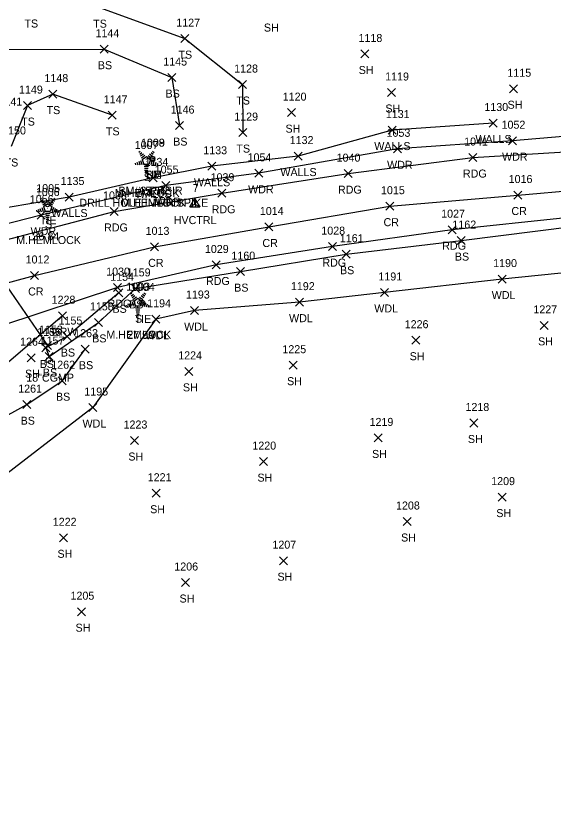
# Model space of a CAD drawing. Extents: x 1621633 to 1624015, y 417863 to 420979.
# Drawn here: x 1622056.7 to 1622191.2, y 417982.6 to 418184 of the extents above; entities that cross this region are included whole.
import ezdxf

# ---------------------------------------------------------------- set-up
doc = ezdxf.new("R2010")
doc.units = 0
for name, color, linetype in [('C_A', 7, 'Continuous'), ('C_C', 7, 'Continuous'), ('C_I', 7, 'Continuous'), ('CBP', 7, 'Continuous'), ('CPBM', 7, 'Continuous'), ('CPSM', 7, 'Continuous'), ('D_A', 7, 'Continuous'), ('D_C', 7, 'Continuous'), ('D_I', 7, 'Continuous'), ('D_TIC', 7, 'Continuous'), ('DCP', 7, 'Continuous'), ('L_A', 7, 'Continuous'), ('L_C', 7, 'Continuous'), ('L_I', 7, 'Continuous'), ('L_TIC', 7, 'Continuous'), ('LAWA', 7, 'Continuous'), ('LELB', 7, 'Continuous'), ('LTC', 7, 'Continuous'), ('LWS', 7, 'Continuous'), ('P_A', 7, 'Continuous'), ('P_I', 7, 'Continuous'), ('P_TIC', 7, 'Continuous'), ('PEU', 7, 'Continuous'), ('PRC', 7, 'Continuous'), ('R_A', 7, 'Continuous'), ('R_I', 7, 'Continuous'), ('R_TIC', 7, 'Continuous'), ('RDW', 7, 'Continuous')]:
    doc.layers.add(name, color=color, linetype=linetype)

msp = doc.modelspace()

# ---------------------------------------------------------------- linework, layer by layer
at = {"layer": 'CBP'}
for centre, radius in [((1622090.77, 418148.39), 0.625), ((1622090.77, 418148.39), 0.0833), ((1622064.59, 418137.03), 0.625), ((1622064.59, 418137.03), 0.0833), ((1622088.28, 418112.35), 0.625), ((1622088.28, 418112.35), 0.0833)]:
    msp.add_circle(centre, radius, dxfattribs=at)
at = {"layer": 'CPBM'}
for p, q in [((1622090.3, 418147.9), (1622090.3, 418148.9)), ((1622090.3, 418148.9), (1622091.3, 418148.9)), ((1622091.3, 418147.9), (1622090.3, 418147.9)), ((1622090.81, 418148.4), (1622090.81, 418148.4)), ((1622090.81, 418148.4), (1622090.81, 418148.4)), ((1622091.3, 418148.9), (1622091.3, 418147.9))]:
    msp.add_line(p, q, dxfattribs=at)
at = {"layer": 'CPSM'}
for p, q in [((1622100.18, 418136.33), (1622101.43, 418138.49)), ((1622102.68, 418136.33), (1622101.43, 418138.49)), ((1622101.43, 418137.05), (1622101.43, 418138.49)), ((1622100.18, 418136.33), (1622101.43, 418137.05)), ((1622100.18, 418136.33), (1622102.68, 418136.33)), ((1622101.43, 418137.05), (1622101.43, 418137.05)), ((1622101.43, 418137.05), (1622102.68, 418136.33))]:
    msp.add_line(p, q, dxfattribs=at)
at = {"layer": 'D_TIC'}
for points in [[(1622063.54, 418100.68), (1622065.54, 418102.68)], [(1622065.54, 418100.68), (1622063.54, 418102.68)]]:
    msp.add_lwpolyline(points, dxfattribs=at)
at = {"layer": 'DCP'}
msp.add_lwpolyline([(1622041.57, 418135.01), (1622064.54, 418101.68)], dxfattribs=at)
at = {"layer": 'L_TIC'}
for points in [[(1622097.9, 418177.4), (1622099.9, 418179.4)], [(1622099.9, 418177.4), (1622097.9, 418179.4)], [(1622077.7, 418174.76), (1622079.7, 418176.76)], [(1622079.7, 418174.76), (1622077.7, 418176.76)], [(1622142.9, 418173.57), (1622144.9, 418175.57)], [(1622144.9, 418173.57), (1622142.9, 418175.57)], [(1622094.64, 418167.67), (1622096.64, 418169.67)], [(1622096.64, 418167.67), (1622094.64, 418169.67)], [(1622112.36, 418165.93), (1622114.36, 418167.93)], [(1622114.36, 418165.93), (1622112.36, 418167.93)], [(1622180.13, 418164.88), (1622182.13, 418166.88)], [(1622182.13, 418164.88), (1622180.13, 418166.88)], [(1622064.92, 418163.54), (1622066.92, 418165.54)], [(1622066.92, 418163.54), (1622064.92, 418165.54)], [(1622149.57, 418163.94), (1622151.57, 418165.94)], [(1622151.57, 418163.94), (1622149.57, 418165.94)], [(1622058.56, 418160.67), (1622060.56, 418162.67)], [(1622060.56, 418160.67), (1622058.56, 418162.67)], [(1622079.75, 418158.24), (1622081.75, 418160.24)], [(1622081.75, 418158.24), (1622079.75, 418160.24)], [(1622124.59, 418158.91), (1622126.59, 418160.91)], [(1622126.59, 418158.91), (1622124.59, 418160.91)], [(1622175.03, 418156.31), (1622177.03, 418158.31)], [(1622177.03, 418156.31), (1622175.03, 418158.31)], [(1622096.55, 418155.67), (1622098.55, 418157.67)], [(1622098.55, 418155.67), (1622096.55, 418157.67)], [(1622112.39, 418153.92), (1622114.39, 418155.92)], [(1622114.39, 418153.92), (1622112.39, 418155.92)], [(1622149.73, 418154.55), (1622151.73, 418156.55)], [(1622151.73, 418154.55), (1622149.73, 418156.55)], [(1622179.88, 418151.89), (1622181.88, 418153.89)], [(1622181.88, 418151.89), (1622179.88, 418153.89)], [(1622126.26, 418148.05), (1622128.26, 418150.05)], [(1622128.26, 418148.05), (1622126.26, 418150.05)], [(1622151.12, 418149.87), (1622153.12, 418151.87)], [(1622153.12, 418149.87), (1622151.12, 418151.87)], [(1622104.64, 418145.5), (1622106.64, 418147.5)], [(1622106.64, 418145.5), (1622104.64, 418147.5)], [(1622089.95, 418142.6), (1622091.95, 418144.6)], [(1622091.95, 418142.6), (1622089.95, 418144.6)], [(1622116.37, 418143.74), (1622118.37, 418145.74)], [(1622118.37, 418143.74), (1622116.37, 418145.74)], [(1622093.14, 418140.69), (1622095.14, 418142.69)], [(1622095.14, 418140.69), (1622093.14, 418142.69)], [(1622068.97, 418137.82), (1622070.97, 418139.82)], [(1622070.97, 418137.82), (1622068.97, 418139.82)], [(1622061.96, 418133.28), (1622063.96, 418135.28)], [(1622063.96, 418133.28), (1622061.96, 418135.28)], [(1622167, 418126.93), (1622169, 418128.93)], [(1622169, 418126.93), (1622167, 418128.93)], [(1622138.27, 418123.52), (1622140.27, 418125.52)], [(1622140.27, 418123.52), (1622138.27, 418125.52)], [(1622111.81, 418119.17), (1622113.81, 418121.17)], [(1622113.81, 418119.17), (1622111.81, 418121.17)], [(1622177.23, 418117.31), (1622179.23, 418119.31)], [(1622179.23, 418117.31), (1622177.23, 418119.31)], [(1622081.36, 418113.88), (1622083.36, 418115.88)], [(1622083.36, 418113.88), (1622081.36, 418115.88)], [(1622085.53, 418114.98), (1622087.53, 418116.98)], [(1622087.53, 418114.98), (1622085.53, 418116.98)], [(1622147.87, 418113.96), (1622149.87, 418115.96)], [(1622149.87, 418113.96), (1622147.87, 418115.96)], [(1622126.56, 418111.54), (1622128.56, 418113.54)], [(1622128.56, 418111.54), (1622126.56, 418113.54)], [(1622100.31, 418109.45), (1622102.31, 418111.45)], [(1622102.31, 418109.45), (1622100.31, 418111.45)], [(1622076.28, 418106.48), (1622078.28, 418108.48)], [(1622078.28, 418106.48), (1622076.28, 418108.48)], [(1622090.62, 418107.26), (1622092.62, 418109.26)], [(1622092.62, 418107.26), (1622090.62, 418109.26)], [(1622187.76, 418105.74), (1622189.76, 418107.74)], [(1622189.76, 418105.74), (1622187.76, 418107.74)], [(1622068.44, 418102.95), (1622070.44, 418104.95)], [(1622070.44, 418102.95), (1622068.44, 418104.95)], [(1622155.64, 418102.03), (1622157.64, 418104.03)], [(1622157.64, 418102.03), (1622155.64, 418104.03)], [(1622063.16, 418100.09), (1622065.16, 418102.09)], [(1622065.16, 418100.09), (1622063.16, 418102.09)], [(1622072.97, 418099.79), (1622074.97, 418101.79)], [(1622074.97, 418099.79), (1622072.97, 418101.79)], [(1622059.44, 418097.66), (1622061.44, 418099.66)], [(1622061.44, 418097.66), (1622059.44, 418099.66)], [(1622063.96, 418097.95), (1622065.96, 418099.95)], [(1622065.96, 418097.95), (1622063.96, 418099.95)], [(1622124.99, 418095.79), (1622126.99, 418097.79)], [(1622126.99, 418095.79), (1622124.99, 418097.79)], [(1622098.94, 418094.24), (1622100.94, 418096.24)], [(1622100.94, 418094.24), (1622098.94, 418096.24)], [(1622067.24, 418091.91), (1622069.24, 418093.91)], [(1622069.24, 418091.91), (1622067.24, 418093.91)], [(1622058.4, 418085.93), (1622060.4, 418087.93)], [(1622060.4, 418085.93), (1622058.4, 418087.93)], [(1622074.89, 418085.21), (1622076.89, 418087.21)], [(1622076.89, 418085.21), (1622074.89, 418087.21)], [(1622170.22, 418081.34), (1622172.22, 418083.34)], [(1622172.22, 418081.34), (1622170.22, 418083.34)], [(1622146.24, 418077.61), (1622148.24, 418079.61)], [(1622148.24, 418077.61), (1622146.24, 418079.61)], [(1622085.28, 418076.96), (1622087.28, 418078.96)], [(1622087.28, 418076.96), (1622085.28, 418078.96)], [(1622117.57, 418071.69), (1622119.57, 418073.69)], [(1622119.57, 418071.69), (1622117.57, 418073.69)], [(1622090.74, 418063.79), (1622092.74, 418065.79)], [(1622092.74, 418063.79), (1622090.74, 418065.79)], [(1622177.3, 418062.82), (1622179.3, 418064.82)], [(1622179.3, 418062.82), (1622177.3, 418064.82)], [(1622153.49, 418056.72), (1622155.49, 418058.72)], [(1622155.49, 418056.72), (1622153.49, 418058.72)], [(1622067.57, 418052.65), (1622069.57, 418054.65)], [(1622069.57, 418052.65), (1622067.57, 418054.65)], [(1622122.58, 418046.93), (1622124.58, 418048.93)], [(1622124.58, 418046.93), (1622122.58, 418048.93)], [(1622098.1, 418041.47), (1622100.1, 418043.47)], [(1622100.1, 418041.47), (1622098.1, 418043.47)], [(1622072.08, 418034.18), (1622074.08, 418036.18)], [(1622074.08, 418034.18), (1622072.08, 418036.18)]]:
    msp.add_lwpolyline(points, dxfattribs=at)
at = {"layer": 'LAWA'}
for points in [[(1622320.21, 418157.08), (1622282.22, 418156.15), (1622251.71, 418155.08), (1622223.6, 418155.09), (1622209.11, 418155.31), (1622180.88, 418152.89), (1622152.12, 418150.87), (1622117.37, 418144.74), (1622094.14, 418141.69), (1622062.96, 418134.28), (1622030.01, 418125.89), (1622002.09, 418113.22), (1622001.94, 418118.19), (1622004.41, 418142.61), (1621992.55, 418166.21), (1621982.92, 418190.96), (1621974.22, 418213.57), (1621987.21, 418225.09), (1622016.71, 418238.58), (1622052.18, 418242.59)], [(1622320.95, 418130.74), (1622294.18, 418128.87), (1622284.86, 418124.81), (1622280.86, 418118.53), (1622268.54, 418119.81), (1622252.02, 418123.74), (1622232.12, 418123.26), (1622206.96, 418121.21), (1622178.23, 418118.31), (1622148.87, 418114.96), (1622127.56, 418112.54), (1622101.31, 418110.45), (1622091.62, 418108.26), (1622075.89, 418086.21), (1622049.19, 418065.74), (1622027.93, 418059.19), (1622009.75, 418042.71)]]:
    msp.add_lwpolyline(points, dxfattribs=at)
at = {"layer": 'LELB'}
for points in [[(1622060.38, 418186.18), (1622077.57, 418186.15), (1622098.9, 418178.4), (1622113.36, 418166.93), (1622113.39, 418154.92)], [(1622048.29, 418155.18), (1622053.86, 418158.66), (1622045.52, 418162.39), (1622052.69, 418175.68), (1622078.7, 418175.76), (1622095.64, 418168.67), (1622097.55, 418156.67)], [(1622080.75, 418159.24), (1622065.92, 418164.54), (1622059.56, 418161.67), (1622055.43, 418151.45)], [(1622082.36, 418114.88), (1622069.44, 418103.95), (1622064.16, 418101.09), (1622064.96, 418098.95), (1622077.28, 418107.48), (1622086.53, 418115.98), (1622112.81, 418120.17), (1622139.27, 418124.52), (1622168, 418127.93), (1622196.43, 418131.51), (1622225.4, 418133.16), (1622251.62, 418128.75), (1622269.47, 418122.5), (1622273.39, 418125.97), (1622269.77, 418128.33), (1622262.73, 418128.05), (1622244.65, 418132.11)], [(1622029.16, 418074.56), (1622043.99, 418078.49), (1622059.4, 418086.93), (1622068.24, 418092.91), (1622073.97, 418100.79)]]:
    msp.add_lwpolyline(points, dxfattribs=at)
at = {"layer": 'LTC'}
for p, q in [((1622087.42, 418150.03), (1622087.77, 418150.28)), ((1622087.63, 418149.56), (1622088.16, 418149.95)), ((1622090.45, 418149.92), (1622091, 418149.52)), ((1622090.82, 418150.27), (1622091.24, 418149.96)), ((1622087.82, 418147.96), (1622088.15, 418146.94)), ((1622087.84, 418149.1), (1622088.54, 418149.61)), ((1622088.05, 418148.63), (1622088.93, 418149.27)), ((1622088.27, 418148.18), (1622089.28, 418148.91)), ((1622088.27, 418148.18), (1622088.66, 418146.98)), ((1622089.28, 418148.91), (1622090.28, 418148.18)), ((1622089.7, 418149.22), (1622090.51, 418148.63)), ((1622090.28, 418148.18), (1622089.89, 418146.98)), ((1622090.08, 418149.57), (1622090.75, 418149.08)), ((1622090.72, 418147.91), (1622090.38, 418146.87)), ((1622086.45, 418147.31), (1622086.6, 418146.84)), ((1622086.91, 418147.52), (1622087.12, 418146.87)), ((1622087.36, 418147.74), (1622087.63, 418146.9)), ((1622089.89, 418146.98), (1622088.66, 418146.98)), ((1622089.85, 418146.48), (1622088.71, 418146.48)), ((1622089.77, 418145.98), (1622088.78, 418145.98)), ((1622091.16, 418147.66), (1622090.88, 418146.78)), ((1622091.61, 418147.41), (1622091.37, 418146.68)), ((1622092.05, 418147.16), (1622091.87, 418146.59)), ((1622089.68, 418145.48), (1622088.85, 418145.48)), ((1622089.6, 418144.98), (1622088.93, 418144.98)), ((1622062.74, 418138.27), (1622063.09, 418138.53)), ((1622062.95, 418137.81), (1622063.48, 418138.19)), ((1622063.16, 418137.34), (1622063.86, 418137.85)), ((1622065.4, 418137.82), (1622066.07, 418137.32)), ((1622065.77, 418138.17), (1622066.32, 418137.77)), ((1622066.14, 418138.51), (1622066.56, 418138.21)), ((1622062.23, 418135.77), (1622062.44, 418135.12)), ((1622062.68, 418135.99), (1622062.95, 418135.15)), ((1622063.14, 418136.2), (1622063.47, 418135.18)), ((1622063.37, 418136.88), (1622064.25, 418137.51)), ((1622063.59, 418136.42), (1622064.6, 418137.16)), ((1622063.59, 418136.42), (1622063.98, 418135.23)), ((1622064.6, 418137.16), (1622065.6, 418136.43)), ((1622065.02, 418137.47), (1622065.83, 418136.88)), ((1622065.6, 418136.43), (1622065.21, 418135.23)), ((1622066.04, 418136.16), (1622065.7, 418135.12)), ((1622066.48, 418135.91), (1622066.2, 418135.02)), ((1622061.77, 418135.55), (1622061.92, 418135.08)), ((1622065.21, 418135.23), (1622063.98, 418135.23)), ((1622065.17, 418134.73), (1622064.03, 418134.73)), ((1622065.09, 418134.23), (1622064.1, 418134.23)), ((1622066.93, 418135.66), (1622066.69, 418134.93)), ((1622067.37, 418135.41), (1622067.19, 418134.83)), ((1622065, 418133.73), (1622064.17, 418133.73)), ((1622064.92, 418133.23), (1622064.25, 418133.23)), ((1622085.29, 418114.62), (1622085.64, 418114.88)), ((1622085.5, 418114.16), (1622086.03, 418114.54)), ((1622085.71, 418113.69), (1622086.41, 418114.2)), ((1622085.92, 418113.23), (1622086.8, 418113.86)), ((1622087.57, 418113.82), (1622088.38, 418113.23)), ((1622087.94, 418114.17), (1622088.62, 418113.67)), ((1622088.32, 418114.51), (1622088.87, 418114.12)), ((1622088.69, 418114.86), (1622089.11, 418114.56)), ((1622084.32, 418111.9), (1622084.47, 418111.43)), ((1622084.78, 418112.12), (1622084.99, 418111.47)), ((1622085.23, 418112.33), (1622085.5, 418111.5)), ((1622085.69, 418112.55), (1622086.02, 418111.53)), ((1622086.14, 418112.77), (1622087.15, 418113.5)), ((1622086.14, 418112.77), (1622086.53, 418111.58)), ((1622087.15, 418113.5), (1622088.15, 418112.78)), ((1622088.15, 418112.78), (1622087.76, 418111.58)), ((1622088.59, 418112.51), (1622088.25, 418111.47)), ((1622089.03, 418112.26), (1622088.75, 418111.37)), ((1622089.48, 418112.01), (1622089.24, 418111.28)), ((1622089.92, 418111.76), (1622089.73, 418111.18)), ((1622087.76, 418111.58), (1622086.53, 418111.58)), ((1622087.72, 418111.08), (1622086.58, 418111.08)), ((1622087.64, 418110.58), (1622086.65, 418110.58)), ((1622087.55, 418110.08), (1622086.72, 418110.08)), ((1622087.47, 418109.58), (1622086.79, 418109.58))]:
    msp.add_line(p, q, dxfattribs=at)
at = {"layer": 'LWS'}
msp.add_lwpolyline([(1622176.03, 418157.31), (1622150.73, 418155.55), (1622127.26, 418149.05), (1622105.64, 418146.5), (1622090.95, 418143.6), (1622069.97, 418138.82), (1622050.21, 418135.43)], dxfattribs=at)
at = {"layer": 'P_TIC'}
for points in [[(1622169.97, 418147.68), (1622171.97, 418149.68)], [(1622171.97, 418147.68), (1622169.97, 418149.68)], [(1622138.72, 418143.66), (1622140.72, 418145.66)], [(1622140.72, 418143.66), (1622138.72, 418145.66)], [(1622107.12, 418138.76), (1622109.12, 418140.76)], [(1622109.12, 418138.76), (1622107.12, 418140.76)], [(1622181.15, 418138.32), (1622183.15, 418140.32)], [(1622183.15, 418138.32), (1622181.15, 418140.32)], [(1622080.22, 418134.22), (1622082.22, 418136.22)], [(1622082.22, 418134.22), (1622080.22, 418136.22)], [(1622149.17, 418135.53), (1622151.17, 418137.53)], [(1622151.17, 418135.53), (1622149.17, 418137.53)], [(1622118.87, 418130.33), (1622120.87, 418132.33)], [(1622120.87, 418130.33), (1622118.87, 418132.33)], [(1622164.78, 418129.65), (1622166.78, 418131.65)], [(1622166.78, 418129.65), (1622164.78, 418131.65)], [(1622090.3, 418125.36), (1622092.3, 418127.36)], [(1622092.3, 418125.36), (1622090.3, 418127.36)], [(1622134.81, 418125.42), (1622136.81, 418127.42)], [(1622136.81, 418125.42), (1622134.81, 418127.42)], [(1622105.7, 418120.83), (1622107.7, 418122.83)], [(1622107.7, 418120.83), (1622105.7, 418122.83)], [(1622060.28, 418118.21), (1622062.28, 418120.21)], [(1622062.28, 418118.21), (1622060.28, 418120.21)], [(1622081.09, 418115.18), (1622083.09, 418117.18)], [(1622083.09, 418115.18), (1622081.09, 418117.18)]]:
    msp.add_lwpolyline(points, dxfattribs=at)
at = {"layer": 'PEU'}
msp.add_lwpolyline([(1622194.17, 418133.58), (1622165.78, 418130.65), (1622135.81, 418126.42), (1622106.7, 418121.83), (1622082.09, 418116.18), (1622052.81, 418106.54), (1622024.04, 418100.48), (1621997.92, 418097.2), (1621996.78, 418104.27), (1621996.21, 418110.35), (1622021.08, 418116.79), (1622048.73, 418126.69), (1622081.22, 418135.22), (1622108.12, 418139.76), (1622139.72, 418144.66), (1622170.97, 418148.68), (1622202.2, 418150.62)], dxfattribs=at)
at = {"layer": 'PRC'}
msp.add_lwpolyline([(1621997.75, 418104.33), (1622030.17, 418110.75), (1622061.28, 418119.21), (1622091.3, 418126.36), (1622119.87, 418131.33), (1622150.17, 418136.53), (1622182.15, 418139.32), (1622212.39, 418141.94), (1622242.91, 418142.53), (1622274.16, 418143.68), (1622303.74, 418144.57), (1622320.76, 418144.65)], dxfattribs=at)
at = {"layer": 'R_TIC'}
for points in [[(1622067.29, 418108.15), (1622069.29, 418110.15)], [(1622069.29, 418108.15), (1622067.29, 418110.15)]]:
    msp.add_lwpolyline(points, dxfattribs=at)
at = {"layer": 'RDW'}
msp.add_lwpolyline([(1622068.29, 418109.15), (1622048.31, 418092.06), (1622031.51, 418075.62), (1622017.28, 418070.42), (1621999.08, 418052.06), (1621978.46, 418032.93), (1621951.05, 418013.18), (1621921.76, 418000.24), (1621894.36, 417990.23), (1621865.95, 417979.75)], dxfattribs=at)

# ---------------------------------------------------------------- texts
at = {"layer": 'C_A'}
for s, p in [('TIE', (1622088.85, 418143.39)), ('BM', (1622089.12, 418143.4)), ('TIE', (1622062.67, 418132.03)), ('HVCTRL', (1622096.13, 418132.05)), ('TIE', (1622086.35, 418107.35))]:
    msp.add_text(s, height=2, dxfattribs=at).set_placement(p)
at = {"layer": 'C_C'}
for s, p in [('BM#2 RRSIR', (1622082.31, 418139.4)), ('15.56', (1622087.54, 418139.39)), ('DRILL HOLE IN RR SPIKE', (1622072.51, 418136.39)), ('M.HEMLOCK', (1622082.99, 418136.4)), ('36.84', (1622060.8, 418128.03)), ('27.99', (1622084.52, 418103.35))]:
    msp.add_text(s, height=2, dxfattribs=at).set_placement(p)
at = {"layer": 'C_I'}
for s, p in [('1008', (1622087.92, 418151.39)), ('1009', (1622087.95, 418151.4)), ('1005', (1622061.74, 418140.03)), ('7', (1622100.87, 418140.05)), ('1004', (1622085.43, 418115.35))]:
    msp.add_text(s, height=2, dxfattribs=at).set_placement(p)
at = {"layer": 'D_A'}
msp.add_text('P', height=2, dxfattribs=at).set_placement((1622063.92, 418096.68))
at = {"layer": 'D_C'}
msp.add_text('18"CGMP', height=2, dxfattribs=at).set_placement((1622059.24, 418092.68))
at = {"layer": 'D_I'}
msp.add_text('1153', height=2, dxfattribs=at).set_placement((1622062.42, 418104.68))
at = {"layer": 'L_A'}
for s, p in [('TS', (1622058.79, 418181.18)), ('TS', (1622075.98, 418181.15)), ('SH', (1622118.67, 418180.17)), ('TS', (1622097.31, 418173.4)), ('BS', (1622077.14, 418170.76)), ('SH', (1622142.39, 418169.57)), ('BS', (1622094.08, 418163.67)), ('TS', (1622111.77, 418161.93)), ('SH', (1622149.06, 418159.94)), ('SH', (1622179.62, 418160.88)), ('TS', (1622064.33, 418159.54)), ('TS', (1622057.97, 418156.67)), ('TS', (1622079.16, 418154.24)), ('SH', (1622124.08, 418154.91)), ('WALLS', (1622171.57, 418152.31)), ('BS', (1622095.99, 418151.67)), ('TS', (1622111.8, 418149.92)), ('WALLS', (1622146.28, 418150.55)), ('WDR', (1622178.24, 418147.89)), ('TS', (1622053.84, 418146.45)), ('WDR', (1622149.48, 418145.87)), ('WALLS', (1622122.8, 418144.05)), ('S', (1622088.61, 418142.82)), ('WALLS', (1622101.18, 418141.5)), ('WALLS', (1622086.5, 418138.6)), ('WDR', (1622114.73, 418139.74)), ('WDR', (1622091.51, 418136.69)), ('WALLS', (1622065.51, 418133.82)), ('S', (1622063.93, 418131.06)), ('WDR', (1622060.32, 418129.28)), ('BS', (1622166.44, 418122.93)), ('BS', (1622137.71, 418119.52)), ('BS', (1622111.25, 418115.17)), ('WDL', (1622175.65, 418113.31)), ('BS', (1622080.8, 418109.88)), ('BS', (1622084.97, 418110.98)), ('WDL', (1622146.28, 418109.96)), ('S', (1622086.48, 418107.41)), ('WDL', (1622124.97, 418107.54)), ('WDL', (1622098.72, 418105.45)), ('BS', (1622075.73, 418102.48)), ('WDL', (1622089.04, 418103.26)), ('SH', (1622187.25, 418101.74)), ('BS', (1622067.88, 418098.95)), ('SH', (1622155.13, 418098.03)), ('BS', (1622062.6, 418096.09)), ('BS', (1622072.41, 418095.79)), ('SH', (1622058.93, 418093.66)), ('BS', (1622063.4, 418093.95)), ('SH', (1622124.48, 418091.79)), ('SH', (1622098.43, 418090.24)), ('BS', (1622066.68, 418087.91)), ('BS', (1622057.84, 418081.93)), ('WDL', (1622073.31, 418081.21)), ('SH', (1622169.7, 418077.34)), ('SH', (1622145.72, 418073.61)), ('SH', (1622084.77, 418072.96)), ('SH', (1622117.06, 418067.69)), ('SH', (1622090.23, 418059.79)), ('SH', (1622176.79, 418058.82)), ('SH', (1622152.98, 418052.72)), ('SH', (1622067.06, 418048.65)), ('SH', (1622122.07, 418042.93)), ('SH', (1622097.58, 418037.47)), ('SH', (1622071.57, 418030.18))]:
    msp.add_text(s, height=2, dxfattribs=at).set_placement(p)
at = {"layer": 'L_C'}
for p in [(1622081.41, 418138.82), (1622056.73, 418127.06), (1622079.28, 418103.41)]:
    msp.add_text('M.HEMLOCK', height=2, dxfattribs=at).set_placement(p)
at = {"layer": 'L_I'}
for s, p in [('1127', (1622096.77, 418181.4)), ('1144', (1622076.57, 418178.76)), ('1118', (1622142.34, 418177.57)), ('1145', (1622093.51, 418171.67)), ('1128', (1622111.24, 418169.93)), ('1115', (1622179.57, 418168.88)), ('1148', (1622063.79, 418167.54)), ('1119', (1622149, 418167.94)), ('1149', (1622057.43, 418164.67)), ('1147', (1622078.62, 418162.24)), ('1120', (1622123.38, 418162.91)), ('1141', (1622052.3, 418161.66)), ('1130', (1622173.82, 418160.31)), ('1146', (1622095.37, 418159.67)), ('1129', (1622111.26, 418157.92)), ('1131', (1622149.17, 418158.55)), ('1052', (1622178.11, 418155.89)), ('1150', (1622053.21, 418154.45)), ('1132', (1622125.13, 418152.05)), ('1053', (1622149.35, 418153.87)), ('1007', (1622086.37, 418150.82)), ('1133', (1622103.52, 418149.5)), ('1134', (1622088.83, 418146.6)), ('1054', (1622114.59, 418147.74)), ('1055', (1622091.37, 418144.69)), ('1135', (1622067.84, 418141.82)), ('1006', (1622061.64, 418139.06)), ('1056', (1622060.13, 418137.28)), ('1162', (1622165.82, 418130.93)), ('1161', (1622137.66, 418127.52)), ('1160', (1622110.55, 418123.17)), ('1190', (1622176.02, 418121.31)), ('1154', (1622080.24, 418117.88)), ('1159', (1622084.39, 418118.98)), ('1191', (1622147.31, 418117.96)), ('1003', (1622084.24, 418115.41)), ('1192', (1622125.43, 418115.54)), ('1193', (1622099.18, 418113.45)), ('1158', (1622075.16, 418110.48)), ('1194', (1622089.49, 418111.26)), ('1227', (1622186.07, 418109.74)), ('1155', (1622067.32, 418106.95)), ('1226', (1622153.89, 418106.03)), ('1156', (1622061.98, 418104.09)), ('1263', (1622071.23, 418103.79)), ('1264', (1622057.7, 418101.66)), ('1157', (1622062.83, 418101.95)), ('1225', (1622123.3, 418099.79)), ('1224', (1622097.25, 418098.24)), ('1262', (1622065.5, 418095.91)), ('1261', (1622057.23, 418089.93)), ('1195', (1622073.77, 418089.21)), ('1218', (1622169.09, 418085.34)), ('1219', (1622145.1, 418081.61)), ('1223', (1622083.58, 418080.96)), ('1220', (1622115.79, 418075.69)), ('1221', (1622089.62, 418067.79)), ('1209', (1622175.52, 418066.82)), ('1208', (1622151.72, 418060.72)), ('1222', (1622065.87, 418056.65)), ('1207', (1622120.81, 418050.93)), ('1206', (1622096.27, 418045.47)), ('1205', (1622070.31, 418038.18))]:
    msp.add_text(s, height=2, dxfattribs=at).set_placement(p)
at = {"layer": 'LTC'}
for p in [(1622089.17, 418147.92), (1622064.49, 418136.17), (1622087.04, 418112.52)]:
    msp.add_text('.', height=1.04, rotation=270, dxfattribs=at).set_placement(p)
at = {"layer": 'P_A'}
for s, p in [('RDG', (1622168.45, 418143.68)), ('RDG', (1622137.2, 418139.66)), ('RDG', (1622105.61, 418134.76)), ('CR', (1622180.58, 418134.32)), ('RDG', (1622078.71, 418130.22)), ('CR', (1622148.6, 418131.53)), ('CR', (1622118.3, 418126.33)), ('RDG', (1622163.27, 418125.65)), ('CR', (1622089.73, 418121.36)), ('RDG', (1622133.3, 418121.42)), ('RDG', (1622104.19, 418116.83)), ('CR', (1622059.71, 418114.21)), ('RDG', (1622079.58, 418111.18))]:
    msp.add_text(s, height=2, dxfattribs=at).set_placement(p)
at = {"layer": 'P_I'}
for s, p in [('1041', (1622168.76, 418151.68)), ('1040', (1622136.86, 418147.66)), ('1039', (1622105.34, 418142.76)), ('1016', (1622179.89, 418142.32)), ('1038', (1622078.45, 418138.22)), ('1015', (1622147.96, 418139.53)), ('1014', (1622117.66, 418134.33)), ('1027', (1622163.01, 418133.65)), ('1013', (1622089.09, 418129.36)), ('1028', (1622133.04, 418129.42)), ('1029', (1622103.92, 418124.83)), ('1012', (1622059.08, 418122.21)), ('1030', (1622079.23, 418119.18))]:
    msp.add_text(s, height=2, dxfattribs=at).set_placement(p)
at = {"layer": 'R_A'}
msp.add_text('DRW', height=2, dxfattribs=at).set_placement((1622065.66, 418104.15))
at = {"layer": 'R_I'}
msp.add_text('1228', height=2, dxfattribs=at).set_placement((1622065.59, 418112.15))

doc.saveas('drawing.dxf')
